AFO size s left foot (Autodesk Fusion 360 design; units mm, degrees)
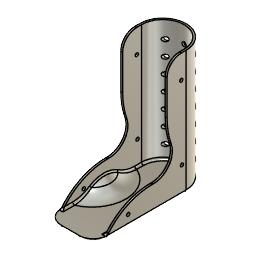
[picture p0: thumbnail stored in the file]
part number: 2025-10-02-12-56-12-317
sketch "Sketch1" plane through (0, 0, 0) normal (0, 0, 1) x axis (1, 0, 0)
  line L1 (-24.5, -98.2) -> (-24.5, 0)
  line L2 (24.5, -98.2) -> (-24.5, -98.2)
  line L3 (24.5, 0) -> (24.5, -98.2)
  line L4 (-22.5, 0) -> (-22.5, -98.2)
  line L5 (22.5, 0) -> (22.5, -98.2)
  line L6 (-22.5, 0) -> (-24.5, 0)
  line L7 (24.5, 0) -> (22.5, 0)
  line L8 (-22.5, -83.2) -> (-24.5, -83.2)
  line L9 (-9.5, -98.2) -> (-9.5, -83.2)
  line L10 (9.5, -98.2) -> (9.5, -83.2)
  line L11 (9.5, -98.2) -> (-9.5, -98.2)
  line L12 (28.7865, -83.2) -> (-12.2135, -83.2)
  circle C1 centre (0, 0) radius 24.5
  circle C2 centre (0, 0) radius 22.5
  circle C3 centre (-9.5, -83.2) radius 15
  circle C4 centre (9.5, -83.2) radius 15
  circle C5 centre (-9.5, -83.2) radius 13
  circle C6 centre (9.5, -83.2) radius 13
  point P1 (0, 0)
  point P2 (0, 0)
  point P3 (-24.5, 0)
  point P6 (24.5, 0)
  point P7 (0, 0)
  point P8 (-22.5, 0)
  point P10 (22.5, 0)
  point P11 (22.5, -98.2)
  point P9 (-22.5, -98.2)
  point P16 (-24.5, -83.2)
  point P17 (-22.5, -83.2)
  point P12 (-9.5, -83.2)
  point P18 (-9.5, -83.2)
  point P19 (-9.5, -98.2)
  point P15 (9.5, -83.2)
  point P20 (9.5, -83.2)
  point P21 (9.5, -98.2)
  point P13 (9.5, -83.2)
  coincident P1 P2
  coincident C1 P3
  tangent C1 L1
  vertical L1
  perpendicular L1 L2
  coincident C1 P6
  tangent C1 L3
  perpendicular L2 L3
  coincident P1 P7
  vertical L4
  coincident C2 P8
  vertical L5
  coincident C2 P10
  perpendicular L4 L6
  perpendicular L3 L7
  coincident L2 P11
  coincident L2 P9
  tangent L3 C4
  tangent L1 C3
  tangent L2 C3
  tangent L2 C4
  concentric C3 C5
  tangent L4 C5
  concentric C4 C6
  tangent L5 C6
  coincident C3 P16
  coincident C5 P17
  coincident L4 P17
  perpendicular L4 L8
  coincident P12 P18
  coincident L2 P19
  coincident C3 P19
  perpendicular L2 L9
  coincident P15 P20
  coincident L2 P21
  coincident C4 P21
  perpendicular L2 L10
  perpendicular L3 L12
  coincident P13 L12
  dimension "d2" diameter C1 = 49 (= "d57 + ( 2 * 2 ) * 1 mm")
  dimension "d4" distance P2 L2 = 98.2
  dimension "d57" diameter C2 = 45
  dimension "d73" diameter C3 = 30
  dimension "d74" diameter C4 = 30
extrude "Extrude1" new body sketch "Sketch1" profile of C1 L1 L3 L4 L5 L6 L7 C3 C4 L8 L12 along normal blind 25
extrude "Extrude2" add sketch "Sketch1" profile of C1 C2 L4 L5 C3 C4 C5 C6 L8 L9 L10 L12 along normal blind 2
extrude "Extrude8" add sketch "Sketch1" profile of L2 C3 C4 L11 along normal blind 2
extrude "Extrude3" add sketch "Sketch1" profile of C1 C2 L6 L7 along normal blind 130
work_plane "WorkPlane3" AlongDistance 40
sphere_primitive "SpherePrimitive3" Diameter 55
move_face "MoveFace3"
boundary_fill "BoundaryFill2"
offset_faces "OffsetFaces3" distance 2
shell "Shell5" innerThickness 2
mirror "Mirror2" mirrorStitchTolerance 0.1
extrude "Extrude16" cut of existing geometry blind -25
delete_face "DeleteFace1"
delete_face "DeleteFace2"
fillet "Fillet31" radius 25
work_plane "WorkPlane1" RotateAngle -90
sketch "Sketch2" plane through (24.5, 0, 0) normal (1, 0, 0) x axis (0, 1, 0)
  line L1 (0, 130) -> (-20, 130)
  line L2 (0, 25) -> (0, 130)
  line L3 (-20, 40) -> (-20, 130)
  line L4 (0, 25) -> (-20, 40)
  circle C1 centre (-5, 105) radius 1.75
  point P2 (0, 25)
  point P6 (0, 25)
  point P4 (0, 130)
  point P7 (0, 130)
  point P3 (-20, 130)
  point P5 (-20, 40)
  point P8 (-5, 105)
  horizontal L1
  perpendicular L1 L2
  perpendicular L1 L3
  coincident P2 P6
  coincident P4 P7
  dimension "d25" distance P3 P4 = 20
  dimension "d28" distance P3 P5 = 90
  dimension "d43" diameter C1 = 3.5
  dimension "d45" distance L3 P8 = 15
  dimension "d47" distance L1 P8 = 25
extrude "Extrude11" add sketch "Sketch2" against normal blind 2
mirror "Mirror1" mirrorStitchTolerance 0.1
work_plane "WorkPlane4" AlongDistance 24.5 (= "22.5 mm + 2 mm")
sketch "Sketch9" plane through (0, 24.5, 0) normal (0, 1, 0) x axis (1, 0, 0)
  circle C1 centre (0, -16) radius 2.25
  circle C2 centre (0, -32) radius 2.25
  circle C3 centre (0, -48) radius 2.25
  circle C4 centre (0, -64) radius 2.25
  circle C5 centre (0, -96) radius 2.25
  circle C6 centre (0, -80) radius 2.25
  circle C7 centre (0, -136) radius 2.5
  circle C8 centre (0, -112) radius 2.25
  point P2 (0, -16)
  point P8 (0, 0)
  point P3 (0, -32)
  point P4 (0, -48)
  point P5 (0, -64)
  point P7 (0, -80)
  point P6 (0, -96)
  point P10 (0, -112)
  dimension "d123" diameter C1 = 4.5
  dimension "d124" diameter C2 = 4.5
  dimension "d125" diameter C3 = 4.5
  dimension "d126" diameter C4 = 4.5
  dimension "d127" diameter C5 = 4.5
  dimension "d128" diameter C6 = 4.5
  dimension "d129" distance P2 P8 = 16
  dimension "d130" distance P2 P3 = 16
  dimension "d131" distance P3 P4 = 16
  dimension "d132" distance P4 P5 = 16 (= "d131")
  dimension "d133" distance P5 P7 = 16 (= "d131")
  dimension "d134" distance P6 P7 = 16 (= "d131")
  dimension "d183" diameter C7 = 5
  dimension "d184" diameter C8 = 4.5
  dimension "d256" distance P6 P10 = 16 (= "d129")
extrude "Extrude12" cut sketch "Sketch9" against normal blind 40
path_pattern "PathPattern2" PathPatternDelta 74
fillet "Fillet28" radius 60
fillet "Fillet18" radius 80
fillet "Fillet34" radius 20
fillet "Fillet35" radius 15
fillet "Fillet36" radius 2
fillet "Fillet37" radius 4
hole "Hole3" HoleDepth 90 HoleDiameter 3.5 TipAngle 118
hole "Hole4" HoleDepth 90 HoleDiameter 3.5 TipAngle 118
fillet "Fillet46" radius 10
fillet "Fillet47" radius 10
fillet "Fillet48" radius 2
fillet "Fillet49" radius 2 2 2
